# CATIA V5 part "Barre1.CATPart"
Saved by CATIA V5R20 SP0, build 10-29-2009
Part number: Base
Publications: "Barre 1", "Pivot1/0", "Pivot1/2"
Bounding box of the stored display mesh (mm): x 0 to 38.743, y -9.948 to 0, z 0 to 5
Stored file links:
  C:\Users\Admin\Desktop\IAO\Barre1.CATPart
  C:\Users\Admin\Desktop\IAO\Skl_4barres.CATProduct
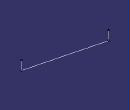
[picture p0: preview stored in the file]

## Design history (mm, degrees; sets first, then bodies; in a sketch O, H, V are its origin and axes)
Set1
  Plane1 "Plan ref": linked copy from another document
  Point1 "Point A": linked copy from another document
  Point2 "Point D": linked copy from another document
Set2
  Line1 "Pivot1/0": type Normal, RefPoint Point1, RefSkin Plane1, Start 0, End 5
  Line2 "Barre 1": type PtPt, FirstPoint Point1, SecondPoint Point2
  Line3 "Pivot1/2": type Normal, RefPoint Point2, RefSkin Plane1, Start 0, End 5
Body1 (main body)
